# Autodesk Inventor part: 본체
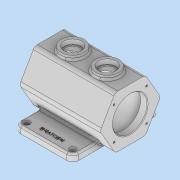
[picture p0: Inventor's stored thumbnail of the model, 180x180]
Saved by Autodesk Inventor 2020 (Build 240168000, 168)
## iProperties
Created: 2021-06
Part Number: 본체
Material: 일반
Document SubType Name: Modeling
Designer: PC2-03
Density: 1 g/cm^3
Appearance: 기본값
Mass: 552.279 g
Surface Area: 1106.53 cm^2
Volume: 552.279 cm^3
Author: PC2-03
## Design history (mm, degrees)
sketch "스케치1"
  geometry: L1 (-50, 75)-(50, 75); L2 (50, 75)-(50, -75); L3 (50, -75)-(-50, -75); L4 (-50, -75)-(-50, 75); 3 further points
  constraints: 8 end point, 2 midpoint, 2 parallel, 1 horizontal, 1 horizontal alignment, 1 perpendicular, 1 vertical alignment
  dimensions: "d0" = 150 distance between parallel lines of L3 L1; "d1" = 100 distance of L2.end L3.end
extrude "돌출1" new body sketch "스케치1" distance "d2" = 12; taper "d3" = 0 deg
sketch "스케치5" dims "d7" = 105
  geometry: L1 (-75, 0)-(75, 0) reference; L2 (26.25, 95.466)-(52.5, 50); L3 (52.5, 50)-(26.25, 4.534); L4 (26.25, 4.534)-(-26.25, 4.534); L5 (-26.25, 4.534)-(-52.5, 50); L6 (-52.5, 50)-(-26.25, 95.466); L7 (-26.25, 95.466)-(26.25, 95.466); 4 further points
  constraints: 12 end point, 1 coincident, 1 horizontal, 1 midpoint, 1 vertical alignment, 16 other
  dimensions: "d6" = 50 distance from line of point (0, 50) L1
extrude "돌출2" join sketch "스케치5" distance "d8" = 65; taper "d10" = 0 deg; dims "d9" = 75, "d11" = 0
node "작업 평면1"
sketch "스케치6"
  geometry: L1 (-75, -26.25)-(-75, 26.25) reference; C1 r 20 at (-35, 0); C2 r 20 at (25, 0); 1 further point
  constraints: 2 centre point, 2 horizontal alignment
  dimensions: "d13" = 40 distance from line of C1.centre L1; "d14" = 40 diameter of C1; "d15" = 40 diameter of C2; "d16" = 60 distance of C1.centre C2.centre
extrude "돌출3" join sketch "스케치6" stored distance "d17" = 65; taper "d18" = 0 deg
sketch "스케치7"
  geometry: C1 r 20 at (0, 0) reference; C2 r 20 at (60, 0) reference; 3 further points
  constraints: 2 coincident
hole "구멍1" sketch "스케치7" at (0, 0), (60, 0) diameter "d19" = 30; stored, may be unused: countersink angle "d23" = 90 deg, drill point angle "d25" = 0 deg; dims "d20" = 6, "d21" = 4, "d22" = 2, "d24" = 8
sketch "스케치8"
  geometry: L1 (75, 50)-(-65, 50); L2 (-50, 0)-(50, 0) reference; L3 (75, 95.466)-(75, 50) reference; L4 (75, 50)-(75, 80); L5 (75, 80)-(63, 80); L6 (63, 80)-(63, 87.5); L7 (63, 87.5)-(-53, 87.5); L8 (-53, 87.5)-(-53, 80); L9 (-53, 80)-(-65, 80); L10 (-65, 50)-(-65, 95.466) reference; L11 (-65, 50)-(-65, 80); 1 further point
  constraints: 16 end point, 6 point on line, 4 perpendicular, 2 horizontal
  dimensions: "d26" = 50 distance between parallel lines of L2 L1; "d27" = 12 distance of L4.end L5.end; "d28" = 12 distance of L8.end L9.end; "d29" = 60 diameter of L5 L1; "d30" = 75 diameter of L7 L1
revolve "회전1" sketch "스케치8" stored, may be unused: angle "d31" = 90 deg
sketch "스케치9"
  geometry: C1 r 15 at (0, 0) reference; 2 further points
  constraints: 1 coincident
hole "구멍2" sketch "스케치9" at (0, 0) diameter "d32" = 25; stored, may be unused: countersink angle "d36" = 90 deg, drill point angle "d38" = 0 deg; dims "d33" = 6, "d34" = 4, "d35" = 2, "d37" = 8
sketch "스케치10"
  geometry: C1 r 15 at (0, 0) reference; 2 further points
  constraints: 1 coincident
hole "구멍3" sketch "스케치10" at (0, 0) diameter "d39" = 25; stored, may be unused: countersink angle "d43" = 90 deg, drill point angle "d45" = 0 deg; dims "d40" = 6, "d41" = 4, "d42" = 2, "d44" = 8
sketch "스케치11"
  geometry: L1 (50, 0)-(50, -40); L2 (50, 0)-(78.284, -28.284); C1 r 30 at (50, 0) reference; A1 r 40 centre (50, 0) between (50, -40) and (78.284, -28.284); 2 further points
  constraints: 4 end point, 2 point on circle, 1 centre point, 1 coincident, 1 concentric, 1 vertical
  dimensions: "d47" = 80 diameter of A1; "d48" = 45 deg angle of L2 L1
hole "구멍4" sketch "스케치11" at (78.284, -28.284) diameter "d49" = 3.242; stored, may be unused: countersink angle "d53" = 90 deg, drill point angle "d55" = 118 deg; dims "d50" = 8, "d51" = 4, "d52" = 2, "d54" = 10
sketch "스케치12" dims "d59" = 80
  geometry: C1 r 30 at (-50, 0) reference; 3 further points
  constraints: 2 vertical alignment, 3 other
hole "구멍5" sketch "스케치12" at (-50, -40) diameter "d60" = 3.242; stored, may be unused: countersink angle "d64" = 90 deg, drill point angle "d66" = 118 deg; dims "d61" = 8, "d62" = 4, "d63" = 2, "d65" = 10
fillet "모깎기1" dims "d70" = 10
sketch "스케치13"
  geometry: A1 r 10 centre (-40, 65) between (-40, 75) and (-50, 65) reference; 2 further points
  constraints: 1 coincident
hole "구멍6" sketch "스케치13" at (-40, 65) diameter "d71" = 11; stored, may be unused: countersink angle "d75" = 90 deg, drill point angle "d77" = 0 deg; dims "d72" = 8, "d73" = 4, "d74" = 2, "d76" = 10
fillet "모깎기2" dims "d90" = 8
chamfer "모따기1" distance "d91" = 1; stored, may be unused: second distance "d92" = 2, angle "d93" = 45 deg
chamfer "모따기2" distance "d94" = 1; stored, may be unused: second distance "d95" = 2, angle "d96" = 45 deg
fillet "모깎기3" dims "d97" = 5
fillet "모깎기4" dims "d98" = 3
fillet "모깎기5" dims "d99" = 3
fillet "모깎기6" dims "d100" = 3
fillet "모깎기7" dims "d101" = 3
fillet "모깎기8" dims "d102" = 3
fillet "모깎기9" dims "d103" = 3
sketch "스케치15"
  geometry: L1 (20.739, 57.998)-(-20.739, 57.998); L2 (-20.739, 57.998)-(-20.739, 64.002); L3 (-20.739, 64.002)-(20.739, 64.002); L4 (20.739, 64.002)-(20.739, 57.998); L5 (20.739, 61)-(-20.739, 61); L6 (0, 57.998)-(0, 64.002); L7 (-50, 65)-(-50, 35.757) reference; L8 (40, 75)-(-40, 75) reference; 1 further point
  constraints: 4 end point, 4 midpoint, 1 horizontal, 2 other
  dimensions: "d104" = 50 distance between parallel lines of L7 L6; "d105" = 6.00407 distance of L1.end L2.end; "d106" = 41.47897 distance of L1.start L1.end; "d107" = 14 distance between parallel lines of L5 L8
feature "엠보싱1" sketch "스케치15" dims "d0" = 150, "d1" = 100, "d108" = 0.5, "d109" = 0
node "솔리드1"
pattern_circular "원형 패턴1" dims angle "d57" = 360 deg
pattern_circular "원형 패턴2" dims angle "d68" = 360 deg
pattern_linear "직사각형 패턴2" dims "d86" = 80, "d89" = 130
feature "A9D066F2-1C7D-4E18-AEED-F7BC21143FA4" dims "d71" = 11, "d72" = 8, "d73" = 4, "d74" = 2, "d75" = 90 deg, "d76" = 10, "d77" = 0
other parameters: "d12" = 102.5
